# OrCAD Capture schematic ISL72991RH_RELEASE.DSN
size A
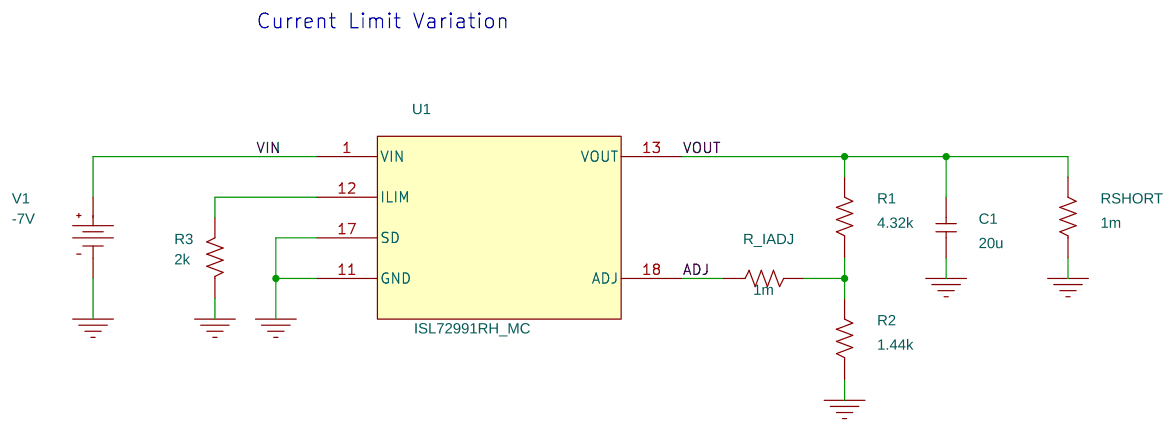
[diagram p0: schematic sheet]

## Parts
C1  20u  [RAD/CK05]
R1  4.32k  [AX/RC05]
R2  1.44k  [AX/RC05]
R3  2k  [AX/RC05]
R_IADJ  1m  [AX/RC05]
RSHORT  1m  [AX/RC05]
U1  ISL72991RH_MC
V1  VDC

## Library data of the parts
C1 = C
R1-R3 R_IADJ RSHORT = R
U1 = ISL72991RH_MC
V1 = VDC: DC: -7V

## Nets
VIN: U1.1(VIN) V1.0(+)
0: C1.1 R2.1 R3.1 RSHORT.1 U1.11(GND) U1.17(SD) V1.1(-)
ADJ: R_IADJ.1 U1.18(ADJ)
VOUT: C1.2 R1.2 RSHORT.2 U1.13(VOUT)
N00072: R3.2 U1.12(ILIM)
N00256: R1.1 R2.2 R_IADJ.2

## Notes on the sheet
- Current Limit Variation
